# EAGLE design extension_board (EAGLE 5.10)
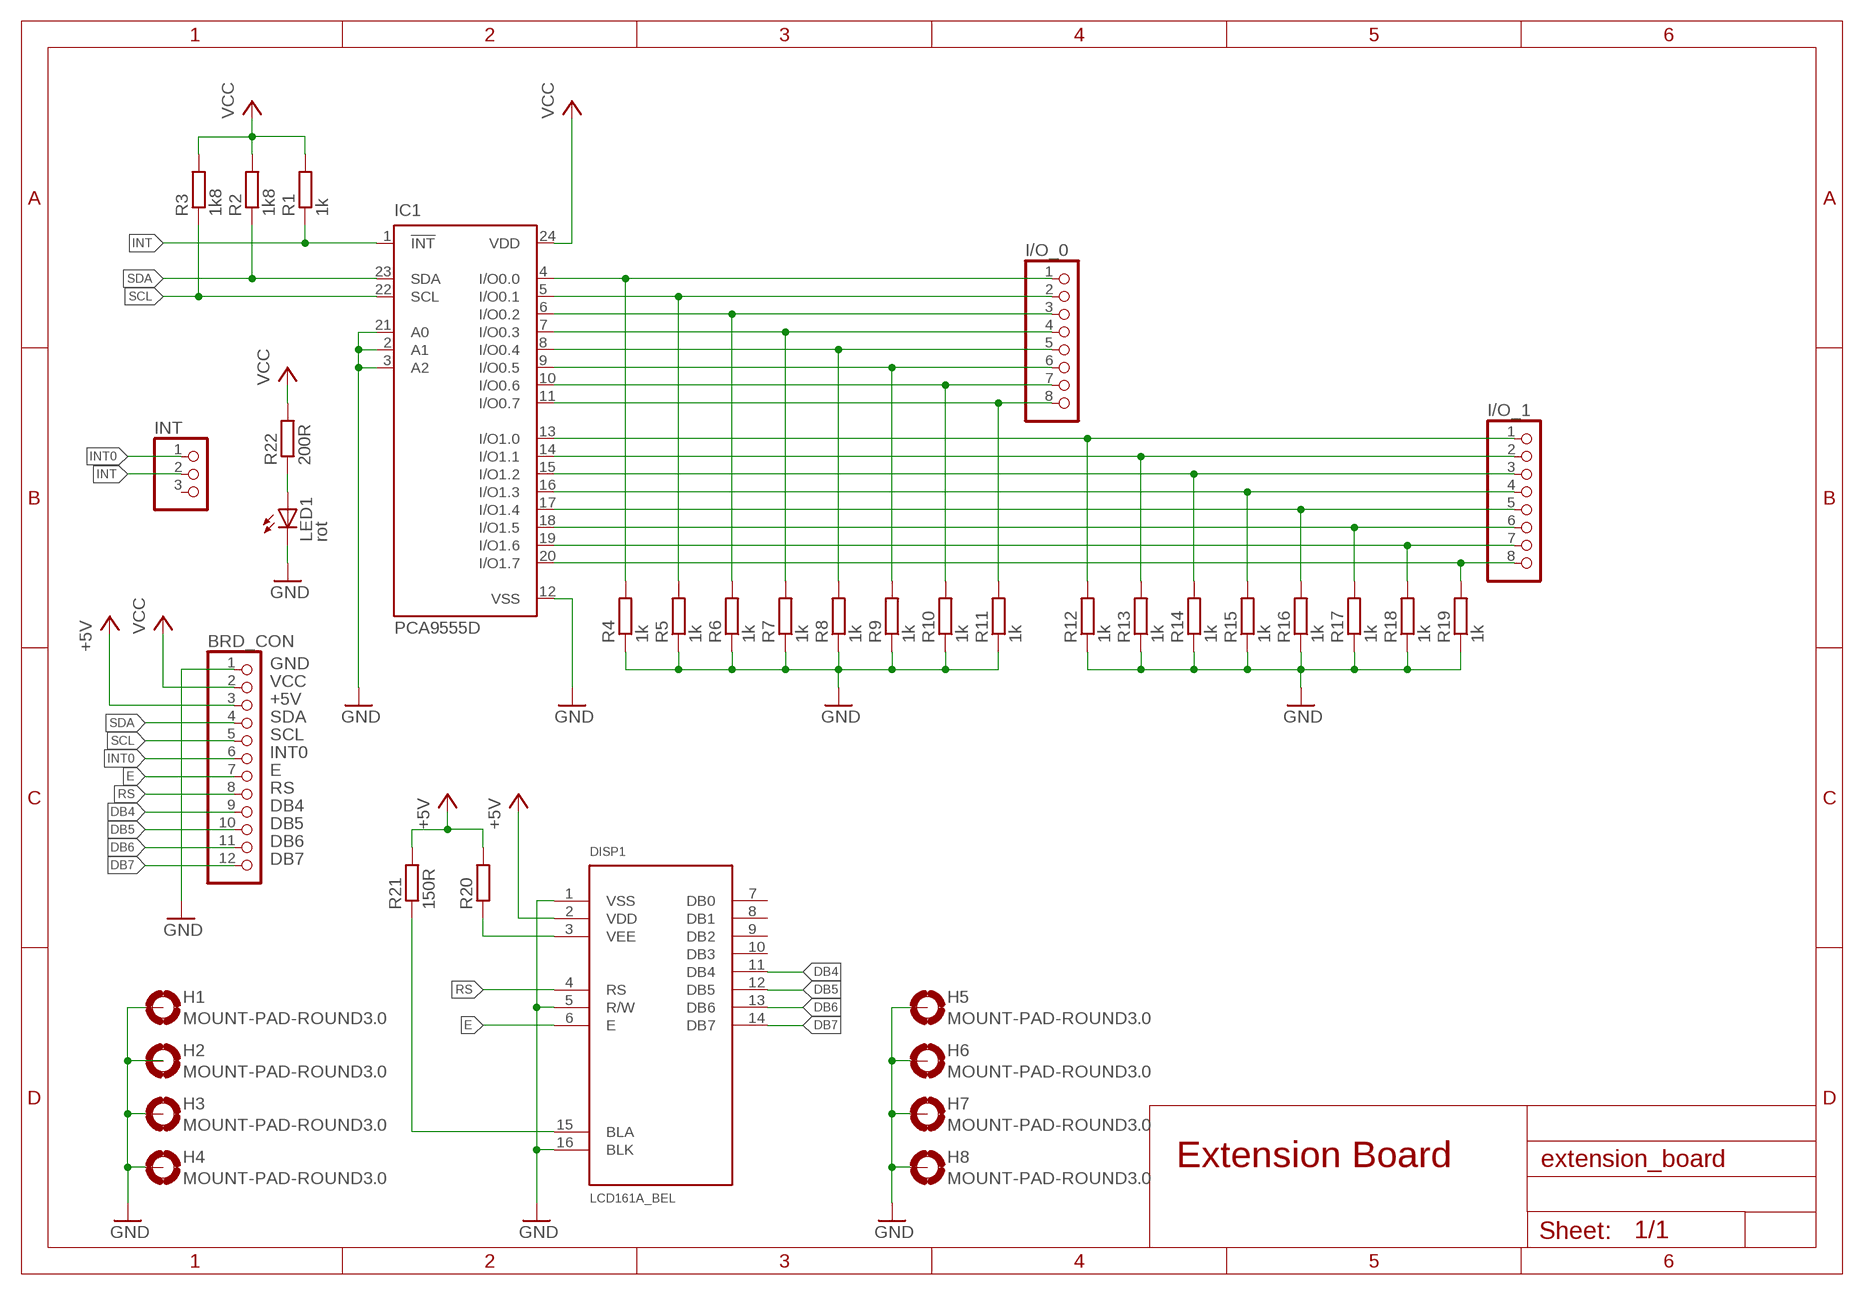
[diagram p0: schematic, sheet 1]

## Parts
BRD_CON  PINHD-1X12  [1X12]
DISP1  LCD161A_BEL  [LCD161A]
H1  MOUNT-PAD-ROUND3.0  [3,0-PAD]
H2  MOUNT-PAD-ROUND3.0  [3,0-PAD]
H3  MOUNT-PAD-ROUND3.0  [3,0-PAD]
H4  MOUNT-PAD-ROUND3.0  [3,0-PAD]
H5  MOUNT-PAD-ROUND3.0  [3,0-PAD]
H6  MOUNT-PAD-ROUND3.0  [3,0-PAD]
H7  MOUNT-PAD-ROUND3.0  [3,0-PAD]
H8  MOUNT-PAD-ROUND3.0  [3,0-PAD]
I/O_0  PINHD-1X8  [1X08]
I/O_1  PINHD-1X8  [1X08]
IC1  PCA9555D  [SO24]
INT  PINHD-1X3  [1X03]
LED1  rot  LED3MM  [LED3MM]
R1  1k  R-EU_0207/12  [0207/12]
R2  1k8  R-EU_0207/12  [0207/12]
R3  1k8  R-EU_0207/12  [0207/12]
R4  1k  R-EU_0207/12  [0207/12]
R5  1k  R-EU_0207/12  [0207/12]
R6  1k  R-EU_0207/12  [0207/12]
R7  1k  R-EU_0207/12  [0207/12]
R8  1k  R-EU_0207/12  [0207/12]
R9  1k  R-EU_0207/12  [0207/12]
R10  1k  R-EU_0207/12  [0207/12]
R11  1k  R-EU_0207/12  [0207/12]
R12  1k  R-EU_0207/12  [0207/12]
R13  1k  R-EU_0207/12  [0207/12]
R14  1k  R-EU_0207/12  [0207/12]
R15  1k  R-EU_0207/12  [0207/12]
R16  1k  R-EU_0207/12  [0207/12]
R17  1k  R-EU_0207/12  [0207/12]
R18  1k  R-EU_0207/12  [0207/12]
R19  1k  R-EU_0207/12  [0207/12]
R20  R-EU_0207/12  [0207/12]
R21  150R  R-EU_0207/12  [0207/12]
R22  200R  R-EU_0207/12  [0207/12]

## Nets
+5V: BRD_CON.3 DISP1.2(VDD) R20.2 R21.2
DB4: BRD_CON.9 DISP1.11(DB4)
DB5: BRD_CON.10 DISP1.12(DB5)
DB6: BRD_CON.11 DISP1.13(DB6)
DB7: BRD_CON.12 DISP1.14(DB7)
E: BRD_CON.7 DISP1.6(E)
GND: BRD_CON.1 DISP1.1(VSS) DISP1.5(R/W) DISP1.16(BLK) H1.B3,0(MOUNT) H3.B3,0(MOUNT) H4.B3,0(MOUNT) H5.B3,0(MOUNT) H6.B3,0(MOUNT) H7.B3,0(MOUNT) H8.B3,0(MOUNT) IC1.2(A1) IC1.3(A2) IC1.12(VSS) IC1.21(A0) LED1.K(C) R4.1 R5.1 R6.1 R7.1 R8.1 R9.1 R10.1 R11.1 R12.1 R13.1 R14.1 R15.1 R16.1 R17.1 R18.1 R19.1
INT: IC1.1(!INT) INT.2 R1.1
INT0: BRD_CON.6 INT.1
N$1: DISP1.3(VEE) R20.1
N$2: LED1.A R22.1
N$3: DISP1.15(BLA) R21.1
N$4: I/O_0.1 IC1.4(I/O0.0) R4.2
N$5: I/O_0.2 IC1.5(I/O0.1) R5.2
N$6: I/O_0.3 IC1.6(I/O0.2) R6.2
N$7: I/O_0.4 IC1.7(I/O0.3) R7.2
N$8: I/O_0.5 IC1.8(I/O0.4) R8.2
N$9: I/O_0.6 IC1.9(I/O0.5) R9.2
N$10: I/O_0.7 IC1.10(I/O0.6) R10.2
N$11: I/O_0.8 IC1.11(I/O0.7) R11.2
N$12: I/O_1.1 IC1.13(I/O1.0) R12.2
N$13: I/O_1.2 IC1.14(I/O1.1) R13.2
N$14: I/O_1.3 IC1.15(I/O1.2) R14.2
N$15: I/O_1.4 IC1.16(I/O1.3) R15.2
N$16: I/O_1.5 IC1.17(I/O1.4) R16.2
N$17: I/O_1.6 IC1.18(I/O1.5) R17.2
N$18: I/O_1.7 IC1.19(I/O1.6) R18.2
N$19: I/O_1.8 IC1.20(I/O1.7) R19.2
RS: BRD_CON.8 DISP1.4(RS)
SCL: BRD_CON.5 IC1.22(SCL) R3.1
SDA: BRD_CON.4 IC1.23(SDA) R2.1
VCC: BRD_CON.2 IC1.24(VDD) R1.2 R2.2 R3.2 R22.2
Unconnected: DISP1.7(DB0) DISP1.8(DB1) DISP1.9(DB2) DISP1.10(DB3) H2.B3,0(MOUNT) INT.3

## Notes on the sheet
- GND
- VCC
- +5V
- SDA
- SCL
- INT0
- E
- RS
- DB4
- DB5
- DB6
- DB7
- Extension Board

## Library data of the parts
BRD_CON = pinhead:PINHD-1X12: PIN HEADER
DISP1 = lcd:LCD161A_BEL: LCD-Display (for example Displaytech) 1x16 LED Background 80x36mm over all
H1-H8 = holes:MOUNT-PAD-ROUND: MOUNTING PAD, round
I/O_0 I/O_1 = pinhead:PINHD-1X8: PIN HEADER
IC1 = micro-philips:PCA9555: 16-bit I2C and SMBus I/O port with interrupt Source: PCA9555_5.pdf
INT = pinhead:PINHD-1X3: PIN HEADER
LED1 = led:LED: LED
R1-R22 = rcl:R-EU_: RESISTOR, European symbol

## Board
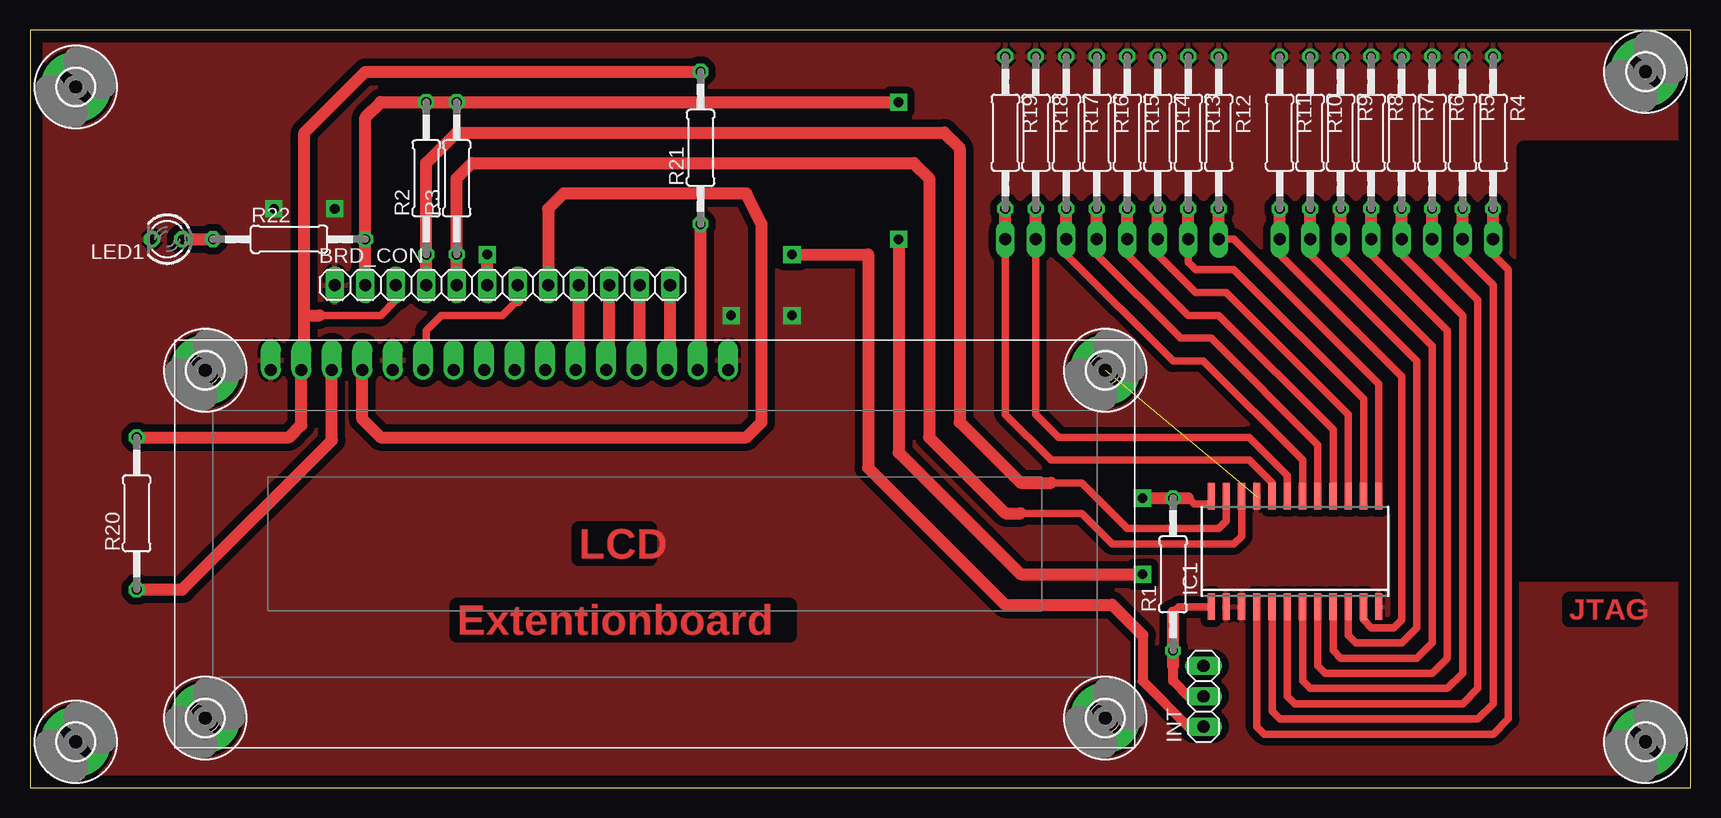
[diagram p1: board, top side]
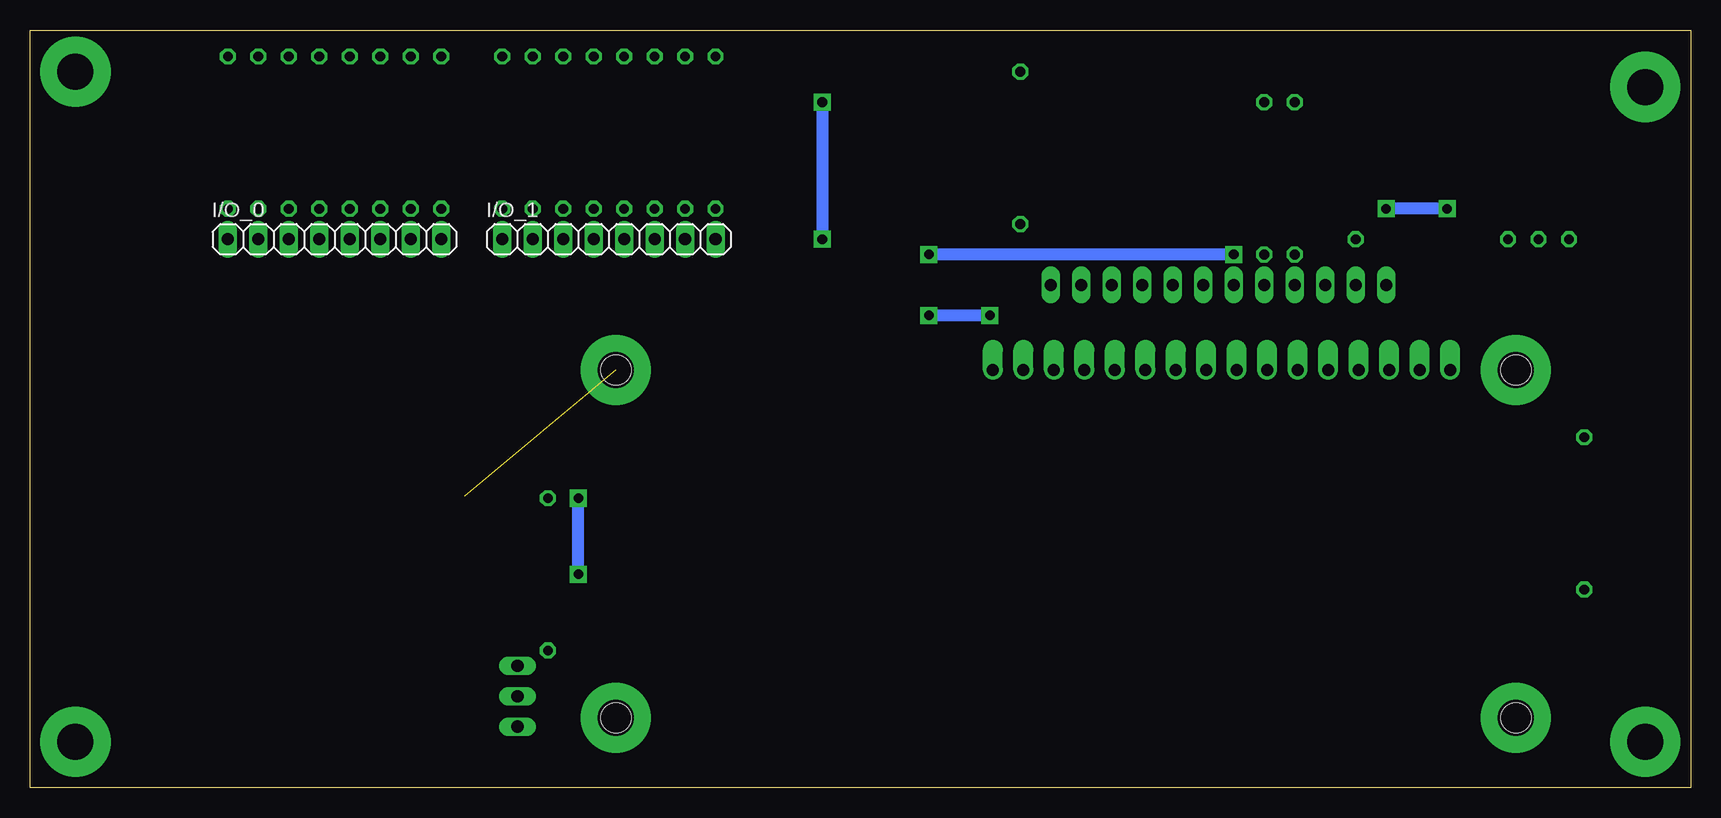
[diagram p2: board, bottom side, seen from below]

Size 138.41 x 63.17 mm. Coordinates in mm from the lower left corner, seen from the top.
Outline: 0,0 138.41,0 138.41,63.17 0,63.17 0,0
Copper layers (1*16): Top 0.035mm / dielectric 1.5mm / Bottom 0.035mm
Design rules "default": minimum track width 10mil, minimum drill 24mil, track to track 8mil, track to pad 8mil, pad to pad 8mil, via to via 8mil, smd to smd 8mil, copper to edge 40mil, drill to drill 8mil, minimum pad ring 10mil, minimum via ring 8mil, stop-mask expansion 4mil, vias tented up to drill 0mil, thermal gap 10mil
tRestrict: area 124.5,17.8 to 138.4,53.3

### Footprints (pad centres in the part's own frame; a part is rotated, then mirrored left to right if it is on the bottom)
1X12 = drill 1.016 long: 1 -13.97,0; 2 -11.43,0; 3 -8.89,0; 4 -6.35,0; 5 -3.81,0; 6 -1.27,0; 7 1.27,0; 8 3.81,0; 9 6.35,0; 10 8.89,0; 11 11.43,0; 12 13.97,0
LCD161A = drill 1 pad 1.676 offset: 1 -32,14.5; 2 -29.46,14.5; 3 -26.92,14.5; 4 -24.38,14.5; 5 -21.84,14.5; 6 -19.3,14.5; 7 -16.76,14.5; 8 -14.22,14.5; 9 -11.68,14.5; 10 -9.14,14.5; 11 -6.6,14.5; 12 -4.06,14.5; 13 -1.52,14.5; 14 1.02,14.5; 15 3.56,14.5; 16 6.1,14.5 | hole 2.5: -37.5,14.5; -37.5,-14.5; 37.5,-14.5; 37.5,14.5
3,0-PAD = drill 3 pad 5.842 round: B3,0 0,0
1X08 = drill 1.016 long: 1 -8.89,0; 2 -6.35,0; 3 -3.81,0; 4 -1.27,0; 5 1.27,0; 6 3.81,0; 7 6.35,0; 8 8.89,0
SO24 = smd 0.6 x 2.2: 1 -6.985,-4.6; 2 -5.715,-4.6; 3 -4.445,-4.6; 4 -3.175,-4.6; 5 -1.905,-4.6; 6 -0.635,-4.6; 7 0.635,-4.6; 8 1.905,-4.6; 9 3.175,-4.6; 10 4.445,-4.6; 11 5.715,-4.6; 12 6.985,-4.6; 13 6.985,4.6; 14 5.715,4.6; 15 4.445,4.6; 16 3.175,4.6; 17 1.905,4.6; 18 0.635,4.6; 19 -0.635,4.6; 20 -1.905,4.6; 21 -3.175,4.6; 22 -4.445,4.6; 23 -5.715,4.6; 24 -6.985,4.6
1X03 = drill 1.016 long: 1 -2.54,0; 2 0,0; 3 2.54,0
LED3MM = drill 0.813 octagon: A -1.27,0; K 1.27,0
0207/12 = drill 0.813 octagon: 1 -6.35,0; 2 6.35,0

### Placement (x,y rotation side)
BRD_CON  39.37,41.91 0 top
DISP1  52.07,20.32 0 top
H1  3.81,3.81 0 top
H2  134.62,59.69 0 top
H3  134.62,3.81 0 top
H4  3.81,58.42 0 top
H5  14.6,5.8 0 top
H6  14.6,34.8 0 top
H7  89.6,34.8 0 top
H8  89.6,5.8 0 top
I/O_0  113.03,45.72 0 bottom
I/O_1  90.17,45.72 0 bottom
IC1  105.41,19.68 0 top
INT  97.79,7.62 90 top
LED1  11.43,45.72 180 top
R1  95.25,17.78 90 top
R2  33.02,50.8 90 top
R3  35.56,50.8 90 top
R4  121.92,54.61 270 top
R5  119.38,54.61 270 top
R6  116.84,54.61 270 top
R7  114.3,54.61 270 top
R8  111.76,54.61 270 top
R9  109.22,54.61 270 top
R10  106.68,54.61 270 top
R11  104.14,54.61 270 top
R12  99.06,54.61 270 top
R13  96.52,54.61 270 top
R14  93.98,54.61 270 top
R15  91.44,54.61 270 top
R16  88.9,54.61 270 top
R17  86.36,54.61 270 top
R18  83.82,54.61 270 top
R19  81.28,54.61 270 top
R20  8.89,22.86 90 top
R21  55.88,53.34 90 top
R22  21.59,45.72 0 top

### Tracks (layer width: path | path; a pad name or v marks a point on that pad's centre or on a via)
+5V
  Top 0.61: BRD_CON.3 30.48,40.64 29.21,39.37 24.13,39.37 | DISP1.2 22.86,35.07
  Top 1.016: 22.61,34.29 22.61,30.23 21.59,29.21 R20.2 | 22.61,34.29 DISP1.2 | R21.2 27.94,59.69 22.86,54.61 22.86,39.37 | 22.86,39.37 22.86,34.54 22.61,34.29 | 22.86,39.37 24.13,39.37
DB4
  Top 1.016: BRD_CON.9 45.72,35.07 DISP1.11
DB5
  Top 1.016: BRD_CON.10 48.26,35.07 DISP1.12
DB6
  Top 1.016: BRD_CON.11 50.8,35.07 DISP1.13
DB7
  Top 1.016: BRD_CON.12 53.34,35.07 DISP1.14
E
  Top 0.61: 33.02,35.07 33.02,38.1 34.29,39.37 39.37,39.37 40.64,40.64
  Top 1.016: 40.64,40.64 BRD_CON.7 | DISP1.6 33.02,35.07
GND  (via drill 0.8 pad 1.42)  (1 unrouted)
  Bottom 1.016: v58.42,39.37 v63.5,39.37 | v20.32,48.26 v25.4,48.26
  pour Top (isolate 0.61): 0,0 0,63.5 138.43,63.5 138.43,0
INT
  Top 0.61: IC1.1 95.73,15.09 95.25,14.61
  Top 0.813: 95.25,10.16 95.25,8.89 96.52,7.62 INT.2
  Top 1.016: 95.25,10.16 R1.1 95.25,14.61
INT0  (via drill 0.8 pad 1.42)
  Top 0.813: 92.71,12.7 92.71,8.89 96.52,5.08 INT.1
  Top 1.016: v63.5,44.45 69.85,44.45 69.85,26.67 81.28,15.24 90.17,15.24 92.71,12.7 | BRD_CON.6 v38.1,44.45
  Bottom 1.016: v38.1,44.45 v63.5,44.45
N$1
  Top 1.016: DISP1.3 25.15,28.96 12.7,16.51 R20.1
N$2
  Top 1.016: LED1.A R22.1
N$3
  Top 1.016: R21.1 55.88,35.07 DISP1.15
N$4
  Top 0.61: IC1.4 102.23,5.08 102.87,4.45 121.92,4.45 123.19,5.71 123.19,43.18 121.92,44.45 I/O_0.1
  Top 1.016: I/O_0.1 R4.2
N$5
  Top 0.61: IC1.5 103.5,6.35 104.14,5.71 120.65,5.71 121.92,6.99 121.92,41.91 119.38,44.45 I/O_0.2
  Top 1.016: I/O_0.2 R5.2
N$6
  Top 0.61: IC1.6 104.78,7.62 105.41,6.99 119.38,6.99 120.65,8.26 120.65,40.64 116.84,44.45 I/O_0.3
  Top 1.016: I/O_0.3 R6.2
N$7
  Top 0.61: IC1.7 106.05,8.89 106.68,8.26 118.11,8.26 119.38,9.53 119.38,39.37 114.3,44.45 I/O_0.4
  Top 1.016: I/O_0.4 R7.2
N$8
  Top 0.61: IC1.8 107.31,10.16 107.95,9.53 116.84,9.53 118.11,10.79 118.11,38.1 111.76,44.45 I/O_0.5
  Top 1.016: I/O_0.5 R8.2
N$9
  Top 0.61: IC1.9 108.58,11.43 109.22,10.79 115.57,10.79 116.84,12.06 116.84,36.83 109.22,44.45 I/O_0.6
  Top 1.016: I/O_0.6 R9.2
N$10
  Top 0.61: IC1.10 109.86,12.7 110.49,12.06 114.3,12.06 115.57,13.34 115.57,35.56 106.68,44.45 I/O_0.7
  Top 1.016: I/O_0.7 R10.2
N$11
  Top 0.61: I/O_0.8 104.14,44.45 114.3,34.29 114.3,13.97 113.67,13.34 111.76,13.34 111.12,13.97 IC1.11
  Top 1.016: I/O_0.8 R11.2
N$12
  Top 0.61: IC1.13 112.39,33.66 100.33,45.72 I/O_1.1
  Top 1.016: I/O_1.1 R12.2
N$13
  Top 0.61: IC1.14 111.12,32.38 100.33,43.18 97.16,43.18 96.52,43.81 I/O_1.2
  Top 1.016: I/O_1.2 R13.2
N$14
  Top 0.61: I/O_1.3 93.98,44.45 97.16,41.27 99.69,41.27 109.86,31.11 IC1.15
  Top 1.016: I/O_1.3 R14.2
N$15
  Top 0.61: I/O_1.4 91.44,44.45 96.52,39.37 99.06,39.37 108.58,29.84 IC1.16
  Top 1.016: I/O_1.4 R15.2
N$16
  Top 0.61: I/O_1.5 88.9,44.45 95.89,37.47 98.42,37.47 107.31,28.57 IC1.17
  Top 1.016: I/O_1.5 R16.2
N$17
  Top 0.61: I/O_1.6 86.36,44.45 95.25,35.56 97.79,35.56 106.05,27.3 IC1.18
  Top 1.016: I/O_1.6 R17.2
N$18
  Top 0.61: I/O_1.7 83.82,31.11 85.72,29.21 101.6,29.21 104.78,26.04 IC1.19
  Top 1.016: I/O_1.7 R18.2
N$19
  Top 0.61: I/O_1.8 81.28,31.11 85.09,27.3 101.6,27.3 103.5,25.4 IC1.20
  Top 1.016: I/O_1.8 R19.2
RS
  Top 1.016: BRD_CON.8 43.18,48.26 44.45,49.53 59.69,49.53 60.96,46.99 60.96,30.48 59.69,29.21 29.21,29.21 27.69,30.73 DISP1.4
SCL
  Top 0.61: IC1.22 100.97,20.95 100.33,20.32 90.17,20.32 87.63,22.86 82.55,22.86
  Top 1.016: BRD_CON.5 R3.1 35.56,50.8 36.83,52.07 73.66,52.07 74.93,50.8 74.93,29.21 81.28,22.86 82.55,22.86
SDA
  Top 0.61: IC1.23 99.69,22.23 99.06,21.59 91.44,21.59 87.63,25.4 85.09,25.4
  Top 1.016: BRD_CON.4 R2.1 33.02,52.07 35.56,54.61 76.2,54.61 77.47,53.34 77.47,30.48 82.55,25.4 85.09,25.4
VCC  (via drill 0.8 pad 1.42)
  Top 0.406: 98.27,23.65 IC1.24
  Top 0.61: 98.27,23.65 97,23.65 96.52,24.13
  Top 1.016: BRD_CON.2 R22.2 27.94,55.88 29.21,57.15 R2.2 R3.2 v72.39,57.15 | 96.52,24.13 R1.2 v92.71,24.13 | v72.39,45.72 72.39,27.94 82.55,17.78 v92.71,17.78
  Bottom 1.016: v92.71,17.78 v92.71,24.13 | v72.39,57.15 v72.39,45.72

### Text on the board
Top: LCD | JTAG | Extentionboard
